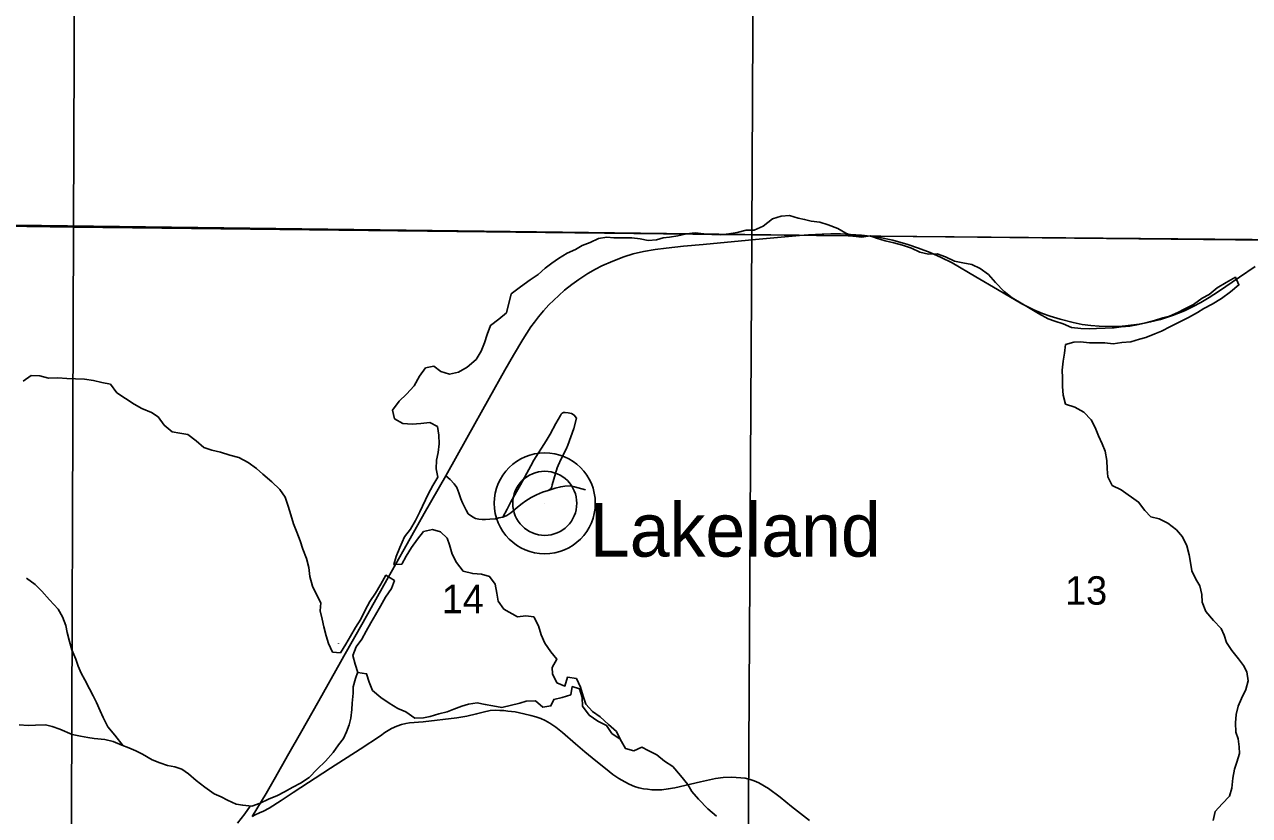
# Model space of a CAD drawing. Extents: x 0 to 191, y 0 to 55.
# Drawn here: x 145.495 to 146.397, y 22.406 to 22.989 of the extents above; entities that cross this region are included whole.
import ezdxf

# ---------------------------------------------------------------- set-up
doc = ezdxf.new("R2010")
doc.units = 0
for name, color, linetype in [('GM_X_Corporation', 7, 'Continuous'), ('GM_X_County_Road', 7, 'Continuous'), ('GM_X_Major_Lake', 7, 'Continuous'), ('GM_X_Minor_River', 7, 'Continuous'), ('GM_X_Section_Text', 7, 'Continuous'), ('GM_X_State_Route', 7, 'Continuous'), ('GM_X_Township_Road', 7, 'Continuous'), ('GM_X_Unincorporated', 7, 'Continuous'), ('GM_X_Unincorporated_Location', 7, 'Continuous'), ('GM_X_Unincorporated_Text', 7, 'Continuous')]:
    doc.layers.add(name, color=color, linetype=linetype)

msp = doc.modelspace()

# ---------------------------------------------------------------- linework, layer by layer
at = {"layer": 'GM_X_Corporation'}
for points in [[(145.53282, 23.34555), (145.53082, 22.83943), (145.03203, 22.84664), (145.03385, 23.35238)], [(145.53282, 23.34555), (146.03304, 23.3384), (146.03039, 22.83378), (145.53082, 22.83943)], [(146.03304, 23.3384), (146.53466, 23.33382), (146.53262, 23.0852), (146.52936, 22.8286), (146.03039, 22.83378)], [(145.03203, 22.84664), (145.53082, 22.83943), (145.52915, 22.33635), (145.02884, 22.34411)], [(145.53082, 22.83943), (146.03039, 22.83378), (146.02757, 22.3284), (145.52915, 22.33635)], [(146.03039, 22.83378), (146.52936, 22.8286), (146.52606, 22.57541), (146.52237, 22.32297), (146.02757, 22.3284)]]:
    msp.add_lwpolyline(points, close=True, dxfattribs=at)
for points in [[(144.13636, 22.86114), (144.77211, 22.85014), (144.77299, 22.85013), (144.90425, 22.84844), (144.9049, 22.84843), (145.16106, 22.84513), (145.16143, 22.84513), (146.06359, 22.8335), (146.06544, 22.83348), (146.11966, 22.83278), (146.12463, 22.83271), (146.42667, 22.82999), (146.4292, 22.82997), (146.43501, 22.82992), (146.43605, 22.82991), (146.53037, 22.82906), (146.52879, 22.68091), (146.52877, 22.67924), (146.52412, 22.06864)], [(146.52412, 22.06864), (146.52877, 22.67924), (146.52879, 22.68091), (146.53037, 22.82906), (146.43605, 22.82991), (146.43501, 22.82992), (146.4292, 22.82997), (146.42667, 22.82999), (146.12463, 22.83271), (146.11966, 22.83278), (146.06544, 22.83348), (146.06359, 22.8335), (145.16143, 22.84513), (145.16106, 22.84513), (144.9049, 22.84843), (144.90425, 22.84844), (144.77299, 22.85013), (144.77211, 22.85014), (144.13636, 22.86114)]]:
    msp.add_lwpolyline(points, dxfattribs=at)
at = {"layer": 'GM_X_County_Road'}
msp.add_lwpolyline([(146.07288, 22.40263), (146.05971, 22.41301), (146.05126, 22.41982), (146.04276, 22.4261), (146.03561, 22.43032), (146.03218, 22.43179), (146.02921, 22.43279), (146.02549, 22.43384), (146.02247, 22.43417), (146.01557, 22.43451), (146.00934, 22.43426), (146.00365, 22.43346), (145.99269, 22.4312), (145.97378, 22.42677), (145.96889, 22.42589), (145.96424, 22.42535), (145.96002, 22.42526), (145.95671, 22.4253), (145.95358, 22.4256), (145.95077, 22.42606), (145.94718, 22.42677), (145.94396, 22.42777), (145.94011, 22.4294), (145.93693, 22.43104), (145.93241, 22.43363), (145.92814, 22.4366), (145.92275, 22.44087), (145.91568, 22.44664), (145.90755, 22.45316), (145.90058, 22.45915), (145.89095, 22.46735), (145.8861, 22.47136), (145.88163, 22.47437), (145.87836, 22.4763), (145.8751, 22.47772), (145.87142, 22.47906), (145.8677, 22.48002), (145.86263, 22.48128), (145.85619, 22.48253), (145.8508, 22.48324), (145.84783, 22.48358), (145.84494, 22.48374), (145.84176, 22.48383), (145.83783, 22.48358), (145.8326, 22.48236), (145.8277, 22.48111), (145.82051, 22.47956), (145.81311, 22.47835), (145.78834, 22.47525), (145.7783, 22.4745), (145.77558, 22.47404), (145.7724, 22.47333), (145.76893, 22.47211), (145.76504, 22.4704), (145.76023, 22.46743), (145.75692, 22.46509), (145.74195, 22.45517), (145.72011, 22.4412), (145.69271, 22.42334), (145.68384, 22.41744), (145.67489, 22.41171), (145.67074, 22.40944), (145.6679, 22.40837), (145.66458, 22.40683), (145.66232, 22.4055)], dxfattribs=at)
at = {"layer": 'GM_X_Major_Lake'}
for points in [[(145.85316, 22.79039), (145.85998, 22.79552), (145.86719, 22.80066), (145.87306, 22.80465), (145.87837, 22.80921), (145.88311, 22.81283), (145.88804, 22.81644), (145.89448, 22.82024), (145.90055, 22.8231), (145.90548, 22.82595), (145.91135, 22.82805), (145.91761, 22.83109), (145.92368, 22.83205), (145.9288, 22.83149), (145.93524, 22.83169), (145.94207, 22.83151), (145.94814, 22.83095), (145.95421, 22.82963), (145.96028, 22.83021), (145.96521, 22.83155), (145.96995, 22.83212), (145.97601, 22.83308), (145.98246, 22.83461), (145.98872, 22.83519), (145.99517, 22.83444), (146.00105, 22.83407), (146.00749, 22.8337), (146.01356, 22.83447), (146.01963, 22.83561), (146.02626, 22.83714), (146.03214, 22.83715), (146.03878, 22.8402), (146.04579, 22.84552), (146.05205, 22.84762), (146.05812, 22.84801), (146.06456, 22.84612), (146.06931, 22.84518), (146.07424, 22.84386), (146.08068, 22.84311), (146.08675, 22.84122), (146.09377, 22.83857), (146.09984, 22.83498), (146.10515, 22.8329), (146.11141, 22.83215), (146.11767, 22.83311), (146.12241, 22.8314), (146.12867, 22.82933), (146.13512, 22.82782), (146.14157, 22.82612), (146.14801, 22.82404), (146.15427, 22.82102), (146.16072, 22.81951), (146.16698, 22.8199), (146.17324, 22.81763), (146.17988, 22.81441), (146.18595, 22.81309), (146.19258, 22.81197), (146.19865, 22.80913), (146.20472, 22.80458), (146.21004, 22.79871), (146.2163, 22.79208), (146.22237, 22.78753), (146.22901, 22.78337), (146.23546, 22.77958), (146.24172, 22.7758), (146.24874, 22.77201), (146.25367, 22.77012), (146.25974, 22.76823), (146.266, 22.76558), (146.27282, 22.76484), (146.27927, 22.76466), (146.28439, 22.76485), (146.29084, 22.76505), (146.29728, 22.76544), (146.30259, 22.76602), (146.30904, 22.7666), (146.3153, 22.76775), (146.32061, 22.76889), (146.32705, 22.7708), (146.33331, 22.77271), (146.33805, 22.77385), (146.34431, 22.77671), (146.34905, 22.77918), (146.35587, 22.78261), (146.36232, 22.78717), (146.36743, 22.78984), (146.37331, 22.79478), (146.37994, 22.79878), (146.38677, 22.80258), (146.38924, 22.79689), (146.38298, 22.79176), (146.37635, 22.78681), (146.36952, 22.78282), (146.36346, 22.77958), (146.35872, 22.77673), (146.35208, 22.77292), (146.34583, 22.76969), (146.339, 22.76626), (146.33237, 22.76284), (146.32725, 22.76093), (146.3208, 22.75827)], [(145.8579, 22.55263), (145.84773, 22.55835), (145.84372, 22.56402), (145.84255, 22.56989), (145.84138, 22.57671), (145.83737, 22.58218), (145.8313, 22.58404), (145.82487, 22.58438), (145.81785, 22.58623), (145.8129, 22.59246), (145.80983, 22.59869), (145.80771, 22.60551), (145.80617, 22.61043), (145.80122, 22.61514), (145.79516, 22.6168), (145.78873, 22.61544), (145.78422, 22.60972), (145.7799, 22.60362), (145.77578, 22.59715), (145.7726, 22.59125), (145.76673, 22.59102), (145.7684, 22.5971), (145.7712, 22.60357), (145.77456, 22.61136), (145.77907, 22.61708), (145.78263, 22.62355), (145.78581, 22.62983), (145.79216, 22.64277), (145.79553, 22.64923), (145.79928, 22.65533), (145.79792, 22.66158), (145.79826, 22.66784), (145.79937, 22.67353), (145.80008, 22.67998), (145.80005, 22.68624), (145.79888, 22.69268), (145.79318, 22.69568), (145.78675, 22.69488), (145.78032, 22.69446), (145.7735, 22.69499), (145.76724, 22.69836), (145.76569, 22.70461), (145.77076, 22.71128), (145.77622, 22.71643), (145.78167, 22.72272), (145.78579, 22.72977), (145.79011, 22.73586), (145.79635, 22.73704), (145.80148, 22.73309), (145.80773, 22.73124), (145.81435, 22.73279), (145.82076, 22.73644), (145.82735, 22.74198), (145.8311, 22.74826), (145.83353, 22.75435), (145.83557, 22.76043), (145.83799, 22.76708), (145.84402, 22.77167), (145.84986, 22.77645), (145.85316, 22.79039)], [(146.3208, 22.75827), (146.31606, 22.75693), (146.30962, 22.75502), (146.30298, 22.75444), (146.29672, 22.75349), (146.29046, 22.75424), (146.28553, 22.75423), (146.27928, 22.75441), (146.27264, 22.75497), (146.26771, 22.75477), (146.26164, 22.75305), (146.2607, 22.74679), (146.25994, 22.74091), (146.25919, 22.73407), (146.25938, 22.72857), (146.25938, 22.72212), (146.25977, 22.71567), (146.26166, 22.70922), (146.26849, 22.70695), (146.27494, 22.70317), (146.28044, 22.69767), (146.28348, 22.69198), (146.28576, 22.68572), (146.28861, 22.67985), (146.2907, 22.67454), (146.29203, 22.66771), (146.29222, 22.66163), (146.29279, 22.65556), (146.29602, 22.6493), (146.30247, 22.64609), (146.31537, 22.637), (146.32011, 22.63094), (146.32448, 22.6262), (146.33055, 22.62469), (146.33681, 22.62147), (146.34326, 22.61674), (146.34781, 22.61143), (146.35104, 22.60479), (146.35275, 22.59834), (146.3537, 22.59246), (146.35465, 22.58639), (146.3575, 22.58032), (146.36054, 22.57539), (146.36187, 22.56895), (146.36225, 22.56344), (146.36491, 22.55662), (146.3706, 22.54979), (146.3761, 22.54392), (146.37838, 22.53918), (146.38009, 22.53368), (146.38408, 22.5278), (146.38901, 22.52155), (146.39262, 22.51681), (146.39508, 22.51207), (146.39623, 22.50543), (146.39433, 22.49897), (146.3913, 22.49251), (146.38884, 22.48682), (146.38733, 22.48074), (146.38676, 22.47448), (146.38696, 22.46765), (146.38885, 22.46272), (146.38943, 22.45684), (146.38962, 22.4519), (146.38773, 22.44564), (146.38602, 22.44051), (146.3847, 22.43387), (146.38413, 22.42647), (146.38243, 22.42058), (146.37693, 22.41488), (146.37182, 22.40918), (146.3703, 22.40272)], [(145.49381, 22.72602), (145.49965, 22.73022), (145.5059, 22.72988), (145.51234, 22.72822), (145.51934, 22.72845), (145.52578, 22.72793), (145.53222, 22.72778), (145.53884, 22.72744), (145.54547, 22.72653), (145.55172, 22.72506), (145.55797, 22.72396), (145.56274, 22.71754), (145.56901, 22.71322), (145.57547, 22.70909), (145.58117, 22.7059), (145.58819, 22.70291), (145.59312, 22.69991), (145.5977, 22.69368), (145.60341, 22.68878), (145.60909, 22.68787), (145.61515, 22.68677), (145.62105, 22.68226), (145.62675, 22.67718), (145.63263, 22.67532), (145.63907, 22.67384), (145.6459, 22.67161), (145.65272, 22.66995), (145.65956, 22.6662), (145.66564, 22.66168), (145.67039, 22.65773), (145.67686, 22.65208), (145.68276, 22.64643), (145.68677, 22.64058), (145.68889, 22.63395), (145.69101, 22.62771), (145.69294, 22.62108), (145.69543, 22.61503), (145.69774, 22.60841), (145.69986, 22.60236), (145.70236, 22.59554), (145.7041, 22.58892), (145.7049, 22.58229), (145.70683, 22.57528), (145.70971, 22.56904), (145.71296, 22.56299), (145.71262, 22.55692), (145.71398, 22.55086), (145.71533, 22.54518), (145.71689, 22.53856), (145.71862, 22.53288), (145.72169, 22.52664), (145.72737, 22.52611), (145.73149, 22.53239), (145.73487, 22.53829), (145.73861, 22.54476), (145.74236, 22.55085), (145.74573, 22.55751), (145.7491, 22.56379), (145.75323, 22.57008), (145.75716, 22.57674), (145.76091, 22.58321), (145.76718, 22.57927), (145.76513, 22.57338), (145.76062, 22.56709), (145.75707, 22.56043), (145.75332, 22.55415), (145.74995, 22.54806), (145.74639, 22.54197), (145.74321, 22.53626), (145.73907, 22.53054), (145.73646, 22.52408), (145.7382, 22.51764), (145.74032, 22.51159), (145.74676, 22.51068), (145.74869, 22.50443), (145.751, 22.49838), (145.75708, 22.4933), (145.76335, 22.48898), (145.76962, 22.48522), (145.77569, 22.48261), (145.78234, 22.4781), (145.78858, 22.47833), (145.7935, 22.47931), (145.79992, 22.48106), (145.80597, 22.48261), (145.81088, 22.48454)], [(145.85958, 22.48905), (145.86432, 22.49039), (145.87115, 22.49078), (145.87665, 22.48604), (145.88253, 22.487), (145.88461, 22.49175), (145.89087, 22.49327), (145.89713, 22.49518), (145.89826, 22.50126), (145.90357, 22.49956), (145.90547, 22.49311), (145.90567, 22.48685), (145.91079, 22.48021), (145.91705, 22.47586), (145.9235, 22.47264), (145.92748, 22.46676), (145.93355, 22.4626), (145.93071, 22.46829), (145.92483, 22.47321), (145.91875, 22.47908), (145.91306, 22.48287), (145.90832, 22.48818), (145.90623, 22.49425), (145.90433, 22.5007), (145.90129, 22.50714), (145.89466, 22.50808), (145.89276, 22.50163), (145.88688, 22.50408), (145.88365, 22.51053), (145.88346, 22.51528), (145.88687, 22.52154), (145.88251, 22.52685), (145.87795, 22.53311), (145.8753, 22.53936), (145.8734, 22.546), (145.86979, 22.55264), (145.86391, 22.5532), (145.8579, 22.55263)], [(145.81088, 22.48454), (145.81692, 22.48685), (145.82183, 22.4884), (145.82807, 22.4892), (145.83413, 22.4881), (145.83982, 22.487), (145.84626, 22.4859), (145.85958, 22.48905)]]:
    msp.add_lwpolyline(points, dxfattribs=at)
at = {"layer": 'GM_X_Minor_River'}
for points in [[(145.56741, 22.45774), (145.56123, 22.46548), (145.55609, 22.47171), (145.55264, 22.47852), (145.55053, 22.48344), (145.54766, 22.48949), (145.54536, 22.4944), (145.54268, 22.49951), (145.53905, 22.50613), (145.53637, 22.51104), (145.53426, 22.51615), (145.53253, 22.52145), (145.52947, 22.52826), (145.52792, 22.53451), (145.52618, 22.54113), (145.5252, 22.54625), (145.52271, 22.55268), (145.51946, 22.55835), (145.51317, 22.56514), (145.50746, 22.57137), (145.50251, 22.57627), (145.49624, 22.58097)], [(145.72598, 22.53276), (145.72595, 22.53285)], [(145.74016, 22.51205), (145.73843, 22.50728), (145.73694, 22.50101), (145.73678, 22.49627), (145.73606, 22.48906), (145.7359, 22.48432), (145.73517, 22.47806), (145.73388, 22.47312), (145.73201, 22.46799), (145.72958, 22.46304), (145.726, 22.45828), (145.72206, 22.45276), (145.71641, 22.44628), (145.71038, 22.44037), (145.70436, 22.43426), (145.69813, 22.43005), (145.69247, 22.42718), (145.68624, 22.42373), (145.68114, 22.42104), (145.67453, 22.41835), (145.66829, 22.41547), (145.66206, 22.41316), (145.65543, 22.41388), (145.65069, 22.4148), (145.64424, 22.41761), (145.63949, 22.42004), (145.63436, 22.42229), (145.62752, 22.42718), (145.62106, 22.43207), (145.61554, 22.43697), (145.6106, 22.44036), (145.60548, 22.44222), (145.60017, 22.44314), (145.59429, 22.44519), (145.58879, 22.44725), (145.58176, 22.45157), (145.57663, 22.454), (145.57151, 22.45625), (145.56639, 22.45812), (145.56012, 22.46073), (145.55387, 22.4624), (145.5461, 22.46312), (145.54136, 22.46385), (145.53605, 22.46477), (145.5298, 22.46606), (145.52069, 22.46999), (145.51519, 22.47185), (145.51007, 22.47315), (145.50288, 22.47292), (145.49739, 22.47251), (145.49076, 22.47304)], [(145.93355, 22.4626), (145.93748, 22.45565), (145.94356, 22.45397), (145.94943, 22.45664), (145.95418, 22.45419), (145.96045, 22.45098), (145.96615, 22.44645), (145.97242, 22.44229), (145.97794, 22.43586), (145.98326, 22.42923), (145.98631, 22.42412), (145.99126, 22.41825), (145.9981, 22.41125), (146.00437, 22.40576)], [(145.66094, 22.41328), (145.65698, 22.40763), (145.65171, 22.40077)]]:
    msp.add_lwpolyline(points, dxfattribs=at)
at = {"layer": 'GM_X_State_Route'}
msp.add_lwpolyline([(145.66232, 22.4055), (145.67267, 22.4225), (145.67874, 22.43292), (145.68941, 22.45204), (145.69807, 22.46697), (145.71158, 22.49086), (145.72752, 22.51922), (145.72994, 22.52353), (145.74408, 22.54863), (145.75948, 22.57594), (145.77663, 22.60631), (145.78901, 22.62865), (145.80499, 22.65647), (145.82047, 22.6842), (145.83691, 22.71357), (145.84866, 22.73423), (145.85494, 22.74528), (145.86192, 22.75682), (145.86765, 22.76603), (145.87042, 22.76962), (145.87339, 22.77339), (145.87694, 22.77795), (145.881, 22.78226), (145.88824, 22.78924), (145.89254, 22.79318), (145.89802, 22.79723), (145.90296, 22.80096), (145.90961, 22.80527), (145.9153, 22.80845), (145.9199, 22.81087), (145.92819, 22.81443), (145.93618, 22.81756), (145.9432, 22.8197), (145.95065, 22.82145), (145.95918, 22.82292), (145.96747, 22.82401), (145.98022, 22.82539), (145.99461, 22.82673), (146.03327, 22.83032), (146.06554, 22.83321), (146.0723, 22.8338), (146.08234, 22.83438), (146.08861, 22.83455), (146.09581, 22.83446), (146.10325, 22.83413), (146.1112, 22.83354), (146.11977, 22.83251), (146.12484, 22.83175), (146.13429, 22.82982), (146.14534, 22.82668), (146.15328, 22.82409), (146.16186, 22.82079), (146.16993, 22.81706), (146.17797, 22.81309), (146.19558, 22.80288), (146.21143, 22.79343), (146.22933, 22.78297), (146.23812, 22.77866), (146.24469, 22.7759), (146.25021, 22.77385), (146.25757, 22.77159), (146.26723, 22.76921), (146.27393, 22.76787), (146.28012, 22.76707), (146.28627, 22.76649), (146.29593, 22.76636), (146.30057, 22.7664), (146.30564, 22.7667), (146.3158, 22.76804), (146.32421, 22.76971), (146.33161, 22.77142), (146.3404, 22.77431), (146.34931, 22.77795), (146.35554, 22.781), (146.36115, 22.78397), (146.36738, 22.78761), (146.37416, 22.79205), (146.38972, 22.80259), (146.40122, 22.81049)], dxfattribs=at)
at = {"layer": 'GM_X_Township_Road'}
for points in [[(145.88983, 22.70123), (145.88954, 22.70077), (145.88606, 22.69483), (145.88202, 22.68709), (145.87904, 22.68211), (145.87002, 22.66783), (145.86782, 22.66375), (145.86, 22.64971), (145.85306, 22.63734), (145.85024, 22.63193), (145.847, 22.62605)], [(145.88793, 22.66407), (145.88999, 22.66879), (145.89377, 22.67605), (145.89498, 22.67902), (145.89939, 22.69123), (145.90124, 22.69893), (145.89974, 22.70108), (145.89767, 22.70217), (145.89513, 22.70281), (145.89289, 22.70312), (145.89175, 22.70305), (145.89077, 22.70254), (145.89013, 22.70169), (145.88983, 22.70123)], [(145.88047, 22.6457), (145.88187, 22.64662), (145.88261, 22.64733), (145.88321, 22.64835), (145.88349, 22.64978), (145.88711, 22.66218), (145.88793, 22.66407)], [(145.90793, 22.64617), (145.89991, 22.64819), (145.8966, 22.649), (145.89282, 22.64885), (145.88975, 22.64835), (145.88551, 22.64736), (145.88047, 22.6457), (145.8763, 22.64438), (145.87184, 22.64246), (145.86797, 22.64048), (145.86398, 22.63795), (145.86121, 22.63594), (145.85913, 22.63431), (145.85304, 22.62903), (145.84993, 22.62721), (145.8484, 22.6265), (145.847, 22.62605), (145.84412, 22.62536), (145.84156, 22.62481), (145.83758, 22.62444), (145.83439, 22.62423), (145.83183, 22.62412), (145.82927, 22.62452), (145.82695, 22.62505), (145.82468, 22.62608), (145.82151, 22.62849), (145.82001, 22.63101), (145.81875, 22.63351), (145.81735, 22.63642), (145.81619, 22.63948), (145.81461, 22.64393), (145.81316, 22.64776), (145.81123, 22.65061), (145.8083, 22.65369), (145.80499, 22.65647)]]:
    msp.add_lwpolyline(points, dxfattribs=at)
at = {"layer": 'GM_X_Unincorporated'}
for radius in [0.0372, 0.02358]:
    msp.add_circle((145.87799, 22.63616), radius, dxfattribs=at)
at = {"layer": 'GM_X_Unincorporated_Location'}
msp.add_line((145.87799, 22.63616), (145.87799, 22.63616), dxfattribs=at)

# ---------------------------------------------------------------- texts
at = {"layer": 'GM_X_Section_Text'}
for s, p in [('13', (146.26115, 22.56154)), ('14', (145.80199, 22.55523))]:
    msp.add_text(s, height=0.020928, rotation=0.00001, dxfattribs=at).set_placement(p)
at = {"layer": 'GM_X_Unincorporated_Text'}
msp.add_text('Lakeland', height=0.039489, rotation=0.00001, dxfattribs=at).set_placement((145.91115, 22.5969))

doc.saveas('drawing.dxf')
